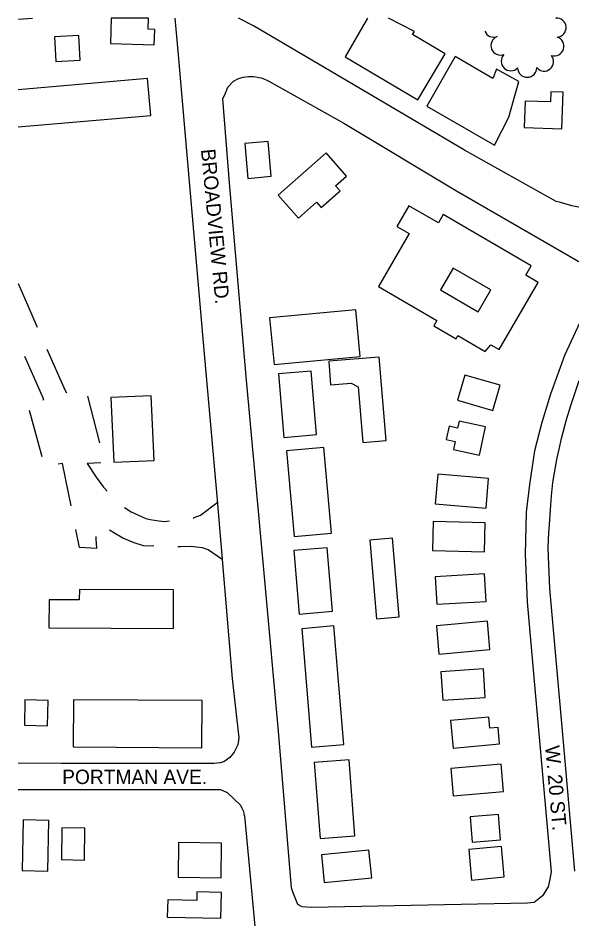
# Model space of a CAD drawing. Extents: x -25029 to 2274964, y -81170 to 687028.
# Drawn here: x -19748 to -19169, y -61689 to -60748 of the extents above; entities that cross this region are included whole.
import ezdxf

# ---------------------------------------------------------------- set-up
doc = ezdxf.new("R2010")
doc.units = 0
for name, color, linetype in [('BLDG', 7, 'Continuous'), ('DRIVWY', 7, 'Continuous'), ('ROAD', 7, 'Continuous'), ('ROAD-NAME', 7, 'Continuous'), ('TREES', 7, 'Continuous')]:
    doc.layers.add(name, color=color, linetype=linetype)

msp = doc.modelspace()

# ---------------------------------------------------------------- linework, layer by layer
at = {"layer": 'BLDG'}
msp.add_line((-19747.86, -60749.43), (-19733.32, -60748.36), dxfattribs=at)
for points in [[(-19651.07, -60748.36), (-19651.8, -60774.98), (-19606, -60776.24), (-19605.56, -60760.28), (-19612.19, -60760.1), (-19611.86, -60748.36)], [(-19611.86, -60748.36), (-19651.07, -60748.36)], [(-19383.14, -60748.36), (-19406.59, -60788.81), (-19330.4, -60833.77), (-19302.12, -60785.83), (-19336.17, -60765.74)], [(-19336.17, -60765.74), (-19334.22, -60762.43), (-19361.22, -60748.36)], [(-19748.36, -60862.16), (-19609.57, -60850.21), (-19612.88, -60811.69), (-19748.36, -60823.36)]]:
    msp.add_lwpolyline(points, dxfattribs=at)
for points in [[(-19683.4, -60792.36), (-19684.95, -60766.65), (-19710.32, -60768.18), (-19708.77, -60793.89)], [(-19235.3, -60851.93), (-19225.19, -60814.77), (-19248.26, -60801.62), (-19252.05, -60811.67), (-19291.54, -60788.65), (-19321.15, -60840.58), (-19250.29, -60880.98)], [(-19191.62, -60825.4), (-19191.96, -60835.89), (-19218.41, -60835.04), (-19219.31, -60862.78), (-19180.04, -60864.04), (-19178.81, -60825.81)], [(-19483.7, -60913.69), (-19487.03, -60877.31), (-19511.45, -60879.55), (-19508.12, -60915.92)], [(-19436.46, -60940.74), (-19431.47, -60946.39), (-19411.79, -60929.01), (-19416.61, -60923.56), (-19405.17, -60913.46), (-19426.52, -60889.28), (-19476.52, -60933.42), (-19455.34, -60957.41)], [(-19310.57, -61064.39), (-19313.81, -61069.94), (-19290.61, -61083.49), (-19288.61, -61080.05), (-19260.27, -61096.61), (-19254.14, -61089.52), (-19245.58, -61094.51), (-19204.67, -61024.46), (-19217.83, -61016.78), (-19212.18, -61007.11), (-19303.92, -60953.53), (-19309.08, -60962.39), (-19339.98, -60944.34), (-19352.59, -60965.94), (-19339.61, -60973.52), (-19371.8, -61028.64)], [(-19254.44, -61032.39), (-19293.72, -61009.57), (-19306.98, -61032.38), (-19267.69, -61055.2)], [(-19395.38, -61053.01), (-19485.42, -61061.58), (-19480.78, -61110.3), (-19390.74, -61101.73)], [(-19423.73, -61106.78), (-19421.74, -61131.31), (-19400.06, -61129.56), (-19392.81, -61133.7), (-19388.12, -61191.69), (-19363.77, -61189.72), (-19370.83, -61102.5)], [(-19476.21, -61119.95), (-19470.58, -61186.29), (-19436.32, -61183.39), (-19441.95, -61117.04)], [(-19252.2, -61158.16), (-19244.64, -61131.91), (-19281.42, -61121.31), (-19288.98, -61147.55)], [(-19651.22, -61144.75), (-19648.36, -61212.36), (-19606.24, -61210.58), (-19609.1, -61142.97)], [(-19287.42, -61169.34), (-19289, -61176.53), (-19297.89, -61174.58), (-19300.94, -61188.46), (-19291.39, -61190.56), (-19293.26, -61199.08), (-19266.22, -61205.03), (-19259.72, -61175.43)], [(-19420.81, -61286.42), (-19428.78, -61196.77), (-19467.7, -61200.23), (-19459.72, -61289.88)], [(-19309.8, -61224.8), (-19312.37, -61255.83), (-19259.14, -61260.25), (-19256.57, -61229.22)], [(-19314.55, -61274.15), (-19315.3, -61304.54), (-19261.05, -61305.87), (-19260.31, -61275.48)], [(-19380.73, -61293.67), (-19373.84, -61375.75), (-19350.19, -61373.77), (-19357.07, -61291.68)], [(-19460.15, -61304.58), (-19454.61, -61370.87), (-19419.77, -61367.96), (-19425.31, -61301.67)], [(-19312.53, -61331.91), (-19310.87, -61360.63), (-19259.13, -61357.65), (-19260.79, -61328.93)], [(-19684.3, -61356.15), (-19715.96, -61355.95), (-19716.15, -61385.12), (-19585.97, -61385.93), (-19585.72, -61345.71), (-19684.23, -61345.09)], [(-19451.94, -61386.12), (-19441.55, -61509.99), (-19408.01, -61507.17), (-19418.4, -61383.3)], [(-19311.14, -61383.08), (-19308.48, -61412.57), (-19255.24, -61407.76), (-19257.9, -61378.27)], [(-19306.48, -61431.08), (-19304.45, -61460.93), (-19260.03, -61457.91), (-19262.06, -61428.05)], [(-19741.69, -61486.98), (-19717.44, -61487.43), (-19716.95, -61461.01), (-19741.2, -61460.56)], [(-19690.69, -61509.6), (-19556.25, -61510.39), (-19555.96, -61461.28), (-19690.4, -61460.48)], [(-19245.18, -61506.5), (-19246.76, -61489.15), (-19255.2, -61489.91), (-19256.24, -61478.43), (-19296.37, -61482.07), (-19293.76, -61510.91)], [(-19396.27, -61602.44), (-19402.46, -61523.15), (-19438.75, -61525.98), (-19432.55, -61605.27)], [(-19296.05, -61532.24), (-19293.58, -61560.81), (-19241.12, -61556.27), (-19243.59, -61527.7)], [(-19275.94, -61582.66), (-19273.78, -61609.06), (-19244.22, -61606.64), (-19246.38, -61580.24)], [(-19743.97, -61638.7), (-19717.11, -61639.27), (-19715.99, -61586.46), (-19742.85, -61585.89)], [(-19703.07, -61627.29), (-19679.03, -61627.73), (-19678.42, -61594.44), (-19702.47, -61594)], [(-19536.03, -61646.26), (-19535.59, -61610.02), (-19580.61, -61609.48), (-19581.04, -61645.71)], [(-19428.45, -61651.29), (-19378.79, -61646.44), (-19381.63, -61617.34), (-19431.3, -61622.19)], [(-19277.36, -61616.77), (-19274.41, -61648.59), (-19240.31, -61645.43), (-19243.26, -61613.61)], [(-19561.41, -61660.93), (-19561.6, -61670.05), (-19591.97, -61669.41), (-19592.35, -61687.3), (-19536.25, -61688.49), (-19535.68, -61661.47)]]:
    msp.add_lwpolyline(points, close=True, dxfattribs=at)
at = {"layer": 'DRIVWY'}
for p, q in [((-19675.69, -61143.43), (-19663.32, -61191.87)), ((-19723.24, -61206.6), (-19736.39, -61158.36))]:
    msp.add_line(p, q, dxfattribs=at)
for points in [[(-19748.36, -61025.48), (-19738.61, -61047.9), (-19728.23, -61071.25)], [(-19722.27, -61147.1), (-19721.4, -61146.93), (-19741.15, -61101.96)], [(-19718.08, -61094.1), (-19698.93, -61137.2), (-19697.77, -61139.79)], [(-19692.93, -61257.91), (-19701.8, -61213.53), (-19706.46, -61214.41)], [(-19661.65, -61212.75), (-19675.96, -61213.69), (-19666.6, -61227.76), (-19659.05, -61238.17), (-19655.16, -61242.62)], [(-19637.01, -61259.52), (-19630.15, -61263.92), (-19614.63, -61271.18), (-19610.42, -61272.14), (-19601.26, -61273.56), (-19594.81, -61274.03), (-19590.17, -61273.61)], [(-19565.45, -61270.68), (-19564.3, -61270.15), (-19557.73, -61267.53), (-19539.34, -61253.71), (-19539.34, -61253.71)], [(-19667.21, -61289.78), (-19667.17, -61292.13), (-19666.82, -61297.45), (-19666.48, -61301.39), (-19666.38, -61302.54), (-19684.24, -61301.36), (-19688.03, -61282.43)], [(-19606.34, -61299.95), (-19617.18, -61299.67), (-19626.89, -61296.48), (-19638.97, -61291.47), (-19648.06, -61285.86), (-19652.59, -61283.35)], [(-19534.99, -61313.87), (-19549.67, -61303.67), (-19555.45, -61301.62), (-19562.14, -61300.83), (-19567.06, -61300.19), (-19578.15, -61300.57), (-19581.35, -61300.52)]]:
    msp.add_lwpolyline(points, dxfattribs=at)
at = {"layer": 'ROAD'}
for points in [[(-19584.63, -60748.36), (-19580.92, -60786.66), (-19573.35, -60875.11), (-19555.05, -61087.14), (-19540.28, -61251.4), (-19524.45, -61438.29), (-19517.67, -61500.13), (-19518.78, -61507.38), (-19522.5, -61514.94), (-19527.12, -61520.6), (-19533.26, -61525.11), (-19536.97, -61526.13), (-19543.23, -61526.74), (-19702.8, -61526.8), (-19748.36, -61526.66)], [(-18852.94, -60748.36), (-18921.93, -60809.72), (-18968.26, -60846.28), (-19024.28, -60883), (-19083.28, -60919.1), (-19118.5, -60938.97), (-19135.46, -60944.82), (-19144.92, -60946.32), (-19151.38, -60947.26), (-19159.22, -60946.46), (-19169.72, -60944.56), (-19181.65, -60941.19), (-19186.02, -60939.87), (-19281.78, -60886.48), (-19378.77, -60829.16), (-19502.42, -60756.67), (-19518, -60748.36)], [(-19152.58, -61047.4), (-19177.36, -61100.7), (-19191.94, -61141.07), (-19200.88, -61170.75), (-19208.61, -61200.5), (-19213.8, -61235.56), (-19217.44, -61264.31), (-19218.56, -61308.75), (-19216.24, -61357.91), (-19210.39, -61425.35), (-19191.38, -61639.95), (-19192.56, -61647.6), (-19194.54, -61655.62), (-19200.33, -61665.19), (-19208.83, -61672.19), (-19216.12, -61672.93), (-19441.54, -61677.26), (-19451.54, -61676.53), (-19455.98, -61674.02), (-19460.92, -61661.85), (-19462.42, -61656.66), (-19476.13, -61492.99), (-19490.29, -61335.83), (-19510.01, -61122.58), (-19527.45, -60920.38), (-19534.19, -60832.62), (-19531.7, -60826.77), (-19528.97, -60820.65), (-19523.13, -60814.4), (-19517.89, -60811.63), (-19513, -60810.25), (-19507.64, -60809.49), (-19502.45, -60809.35), (-19494.19, -60810.77), (-19489.13, -60813.05), (-19486.37, -60814.46), (-19407.97, -60858.34), (-19290.07, -60928.82), (-19149.25, -61010.35)], [(-19166.66, -61639.34), (-19179.51, -61492.86), (-19192.69, -61344.29), (-19194.1, -61311.03), (-19194.26, -61301.15), (-19193.64, -61286.05), (-19193.04, -61277.36), (-19191.93, -61261.84), (-19190.72, -61247.24), (-19189.34, -61233.35), (-19185.33, -61209.52), (-19183.04, -61198.74), (-19180.36, -61187.58), (-19175.24, -61167.72), (-19170.58, -61152.97), (-19161.95, -61126.82)], [(-19748.36, -61554.19), (-19536.63, -61554.05), (-19529.84, -61557.05), (-19515.93, -61570.36), (-19514.61, -61573.52), (-19512.73, -61577.17), (-19511.88, -61581.09), (-19511.69, -61581.49), (-19499.64, -61711.91), (-19492.41, -61809.31), (-19493.01, -61817.15), (-19493.56, -61818.55), (-19498.82, -61825.91), (-19505.07, -61832.08), (-19518.12, -61839.27), (-19521.81, -61840.87), (-19523.16, -61841.06), (-19664.26, -61840.78), (-19748.36, -61840.47)]]:
    msp.add_lwpolyline(points, dxfattribs=at)
at = {"layer": 'TREES'}
for centre, start, end in [((-19186.73, -60738.42), 271.95583, 275.91189), ((-19185.63, -60758.38), 274.31972, 94.31972), ((-19251.28, -60758.41), 202.39108, 290.22865), ((-19244.19, -60777.11), 111.29049, 291.29049), ((-19187.89, -60777.89), 252.48171, 72.48171), ((-19233.44, -60793.44), 135.43811, 315.43811), ((-19198.61, -60793.8), 219.57952, 39.57952), ((-19216.31, -60800.31), 180.82659, 0.82659)]:
    msp.add_arc(centre, 10, start, end, dxfattribs=at)

# ---------------------------------------------------------------- texts
at = {"layer": 'ROAD-NAME'}
for s, height, rotation, p in [('BROADVIEW RD.', 15, 275.36427, (-19557.25, -60885.67)), ('W. 20 ST.', 15, 275.08571, (-19197.59, -61508.82)), ('PORTMAN AVE.', 14.99, 359.97963, (-19702.22, -61548.33))]:
    msp.add_text(s, height=height, rotation=rotation, dxfattribs=at).set_placement(p)

doc.saveas('drawing.dxf')
